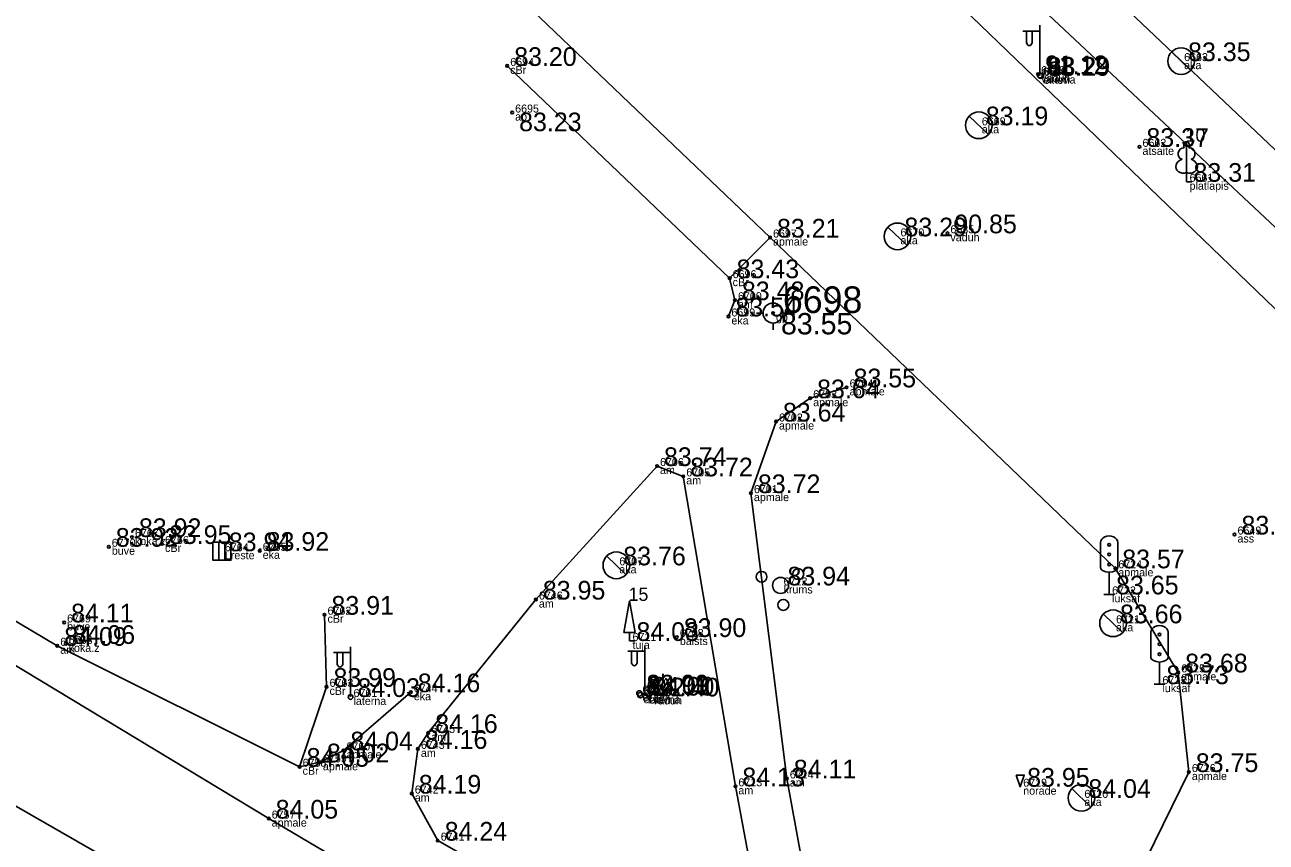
# Model space of a CAD drawing. Extents: x 614911 to 615803, y 262110 to 264311.
# Drawn here: x 615198.38 to 615244.91, y 262569.35 to 262599.99 of the extents above; entities that cross this region are included whole.
import ezdxf

# ---------------------------------------------------------------- set-up
doc = ezdxf.new("R2010")
doc.units = 0
for name, color, linetype in [('Level 1', 7, 'Continuous'), ('Level 12', 7, 'Continuous'), ('Level 16', 7, 'Continuous'), ('Level 19', 7, 'Continuous'), ('Level 37', 7, 'Continuous'), ('Level 44', 7, 'Continuous'), ('Level 48', 7, 'Continuous'), ('Level 53', 7, 'Continuous'), ('Level 54', 7, 'Continuous'), ('Level 57', 7, 'Continuous'), ('Level 58', 7, 'Continuous'), ('Level 7', 7, 'Continuous')]:
    doc.layers.add(name, color=color, linetype=linetype)

msp = doc.modelspace()

# ---------------------------------------------------------------- linework, layer by layer
at = {"layer": 'Level 1'}
for p, q in [((615241.925, 262594.455), (615241.925, 262594.108)), ((615241.925, 262594.108), (615242.125, 262594.108)), ((615221.048, 262576.897), (615221.048, 262577.217)), ((615221.048, 262576.897), (615221.258, 262576.897))]:
    msp.add_line(p, q, dxfattribs=at)
for points in [[(615241.925, 262595.608), (615241.925, 262594.455)], [(615242.015, 262595.376), (615242.014, 262595.377)]]:
    msp.add_lwpolyline(points, dxfattribs=at)
msp.add_lwpolyline([(615220.838, 262577.217), (615221.258, 262577.217), (615221.048, 262578.397)], close=True, dxfattribs=at)
for centre, radius in [((615225.994, 262579.301), 0.204), ((615226.708, 262578.977), 0.301), ((615227.369, 262579.402), 0.207), ((615226.811, 262578.249), 0.205)]:
    msp.add_circle(centre, radius, dxfattribs=at)
for centre, major_axis, ratio, start_param, end_param in [((615241.925, 262595.458), (0, -0.15), 0.707107, 3.14537, 5.287485), ((615241.925, 262595.458), (0, -0.15), 0.707107, 0.995701, 3.137816), ((615241.797, 262595.163), (-0.039, -0.212), 0.861323, 3.141593, 6.283185), ((615242.053, 262595.163), (0.039, -0.212), 0.861323, 0, 3.141593), ((615241.835, 262594.701), (0.307, 0.095), 0.814445, 1.570796, 4.752015), ((615242.015, 262594.701), (-0.307, 0.095), 0.814445, 1.531171, 4.712389)]:
    msp.add_ellipse(centre, major_axis=major_axis, ratio=ratio, start_param=start_param, end_param=end_param, dxfattribs=at)
at = {"layer": 'Level 12'}
for p, q in [((615241.362, 262598.978), (615242.08, 262598.282)), ((615241.721, 262598.63), (615241.72, 262598.629)), ((615233.78, 262596.572), (615234.498, 262595.876)), ((615234.139, 262596.224), (615234.138, 262596.223)), ((615230.732, 262592.41), (615231.45, 262591.714)), ((615231.091, 262592.062), (615231.09, 262592.061)), ((615220.194, 262580.079), (615220.912, 262579.383)), ((615220.553, 262579.731), (615220.552, 262579.73)), ((615238.81, 262577.906), (615239.528, 262577.21)), ((615239.169, 262577.558), (615239.168, 262577.557)), ((615237.624, 262571.362), (615238.342, 262570.666)), ((615237.983, 262571.014), (615237.982, 262571.013))]:
    msp.add_line(p, q, dxfattribs=at)
for centre in [(615241.721, 262598.63), (615234.139, 262596.224), (615231.091, 262592.062), (615220.553, 262579.731), (615239.169, 262577.558), (615237.983, 262571.014)]:
    msp.add_circle(centre, 0.5, dxfattribs=at)
at = {"layer": 'Level 16'}
for p, q in [((615238.701, 262580.591), (615238.701, 262579.645)), ((615239.343, 262580.591), (615239.343, 262579.645)), ((615239.022, 262579.471), (615239.022, 262578.642)), ((615238.822, 262578.642), (615239.022, 262578.642)), ((615239.022, 262578.642), (615239.222, 262578.642)), ((615240.588, 262577.227), (615240.588, 262576.281)), ((615241.23, 262577.227), (615241.23, 262576.281)), ((615240.909, 262576.107), (615240.909, 262575.278)), ((615240.709, 262575.278), (615240.909, 262575.278)), ((615240.909, 262575.278), (615241.109, 262575.278))]:
    msp.add_line(p, q, dxfattribs=at)
for centre in [(615239.022, 262580.502), (615239.022, 262580.142), (615239.022, 262579.762), (615240.909, 262577.138), (615240.909, 262576.778), (615240.909, 262576.398)]:
    msp.add_circle(centre, 0.05, dxfattribs=at)
for centre, ratio, start_param, end_param in [((615239.022, 262580.591), 0.760342, 0, 3.141593), ((615239.022, 262579.645), 0.542056, 3.141593, 6.283185), ((615240.909, 262577.227), 0.760342, 0, 3.141593), ((615240.909, 262576.281), 0.542056, 3.141593, 6.283185)]:
    msp.add_ellipse(centre, major_axis=(0.321, 0), ratio=ratio, start_param=start_param, end_param=end_param, dxfattribs=at)
at = {"layer": 'Level 19'}
for p, q in [((615226.425, 262589.563), (615226.425, 262589.813)), ((615225.8, 262589.188), (615226.05, 262589.188)), ((615226.8, 262589.188), (615227.05, 262589.188)), ((615226.425, 262588.563), (615226.425, 262588.813))]:
    msp.add_line(p, q, dxfattribs=at)
for radius in [0.375, 0.05]:
    msp.add_circle((615226.425, 262589.188), radius, dxfattribs=at)
at = {"layer": 'Level 37'}
msp.add_line((615224.8, 262590.494), (615226.313, 262592.017), dxfattribs=at)
for points in [[(615229.035, 262607.61), (615228.582, 262606.525), (615229.192, 262604.807), (615247.893, 262586.794), (615249.003, 262588.575), (615248.819, 262589.059)], [(615226.458, 262563.733), (615225.015, 262571.448), (615223.063, 262583.066), (615222.077, 262583.453), (615217.538, 262578.448), (615213.503, 262573.447), (615213.116, 262572.851), (615212.887, 262571.176), (615213.858, 262569.412), (615221.288, 262565.152), (615224.887, 262563.845)]]:
    msp.add_lwpolyline(points, close=True, dxfattribs=at)
for points in [[(615281.103, 262578.829), (615274.198, 262576.959), (615266.8, 262577.244), (615261.124, 262580.267), (615236.703, 262603.415), (615232.202, 262607.71)], [(615229.462, 262561.056), (615236.907, 262564.656), (615239.467, 262566.806), (615242.011, 262571.983), (615241.612, 262575.718), (615239.254, 262579.62), (615226.313, 262592.017), (615217.13, 262600.787)], [(615216.464, 262598.45), (615224.8, 262590.494), (615224.999, 262589.668), (615224.753, 262589.059)], [(615208.683, 262572.181), (615199.6, 262576.716), (615192.986, 262580.641), (615185.727, 262585.487), (615185.75, 262586.016), (615181.977, 262588.379), (615178.877, 262590.297)], [(615177.494, 262588.45), (615192.153, 262579.526), (615207.523, 262570.238), (615220.011, 262562.863), (615221.634, 262562.045), (615224.342, 262561.098), (615229.242, 262561.003), (615229.462, 262561.056)], [(615229.183, 262586.402), (615227.818, 262585.994), (615226.537, 262585.121), (615225.598, 262582.438), (615226.943, 262571.742), (615228.392, 262563.814), (615235.188, 262566.685)], [(615216.216, 262560.276), (615189.988, 262575.33), (615174.111, 262583.87)], [(615212.85, 262574.975), (615210.324, 262572.795), (615209.444, 262572.348), (615208.683, 262572.181), (615209.693, 262575.176), (615209.616, 262577.88)]]:
    msp.add_lwpolyline(points, dxfattribs=at)
at = {"layer": 'Level 44'}
for p, q in [((615236.426, 262599.757), (615235.791, 262599.752)), ((615235.926, 262599.753), (615235.926, 262599.361)), ((615236.136, 262599.755), (615236.136, 262599.361)), ((615236.426, 262598.09), (615236.426, 262599.973)), ((615210.591, 262576.464), (615209.956, 262576.459)), ((615210.091, 262576.46), (615210.091, 262576.068)), ((615210.301, 262576.462), (615210.301, 262576.068)), ((615210.591, 262574.797), (615210.591, 262576.68)), ((615221.622, 262576.515), (615220.987, 262576.51)), ((615221.122, 262576.511), (615221.122, 262576.119)), ((615221.332, 262576.513), (615221.332, 262576.119)), ((615221.622, 262574.848), (615221.622, 262576.731))]:
    msp.add_line(p, q, dxfattribs=at)
for centre in [(615236.426, 262598.09), (615210.591, 262574.797), (615221.622, 262574.848)]:
    msp.add_circle(centre, 0.09, dxfattribs=at)
for centre in [(615236.031, 262599.361), (615210.196, 262576.068), (615221.227, 262576.119)]:
    msp.add_ellipse(centre, major_axis=(0, 0.151), ratio=0.695971, start_param=1.570796, end_param=4.712389, dxfattribs=at)
at = {"layer": 'Level 48'}
for p, q in [((615205.655, 262580.597), (615205.655, 262579.922)), ((615205.88, 262580.597), (615205.88, 262579.922))]:
    msp.add_line(p, q, dxfattribs=at)
msp.add_lwpolyline([(615205.43, 262580.597), (615206.105, 262580.597), (615206.105, 262579.922), (615205.43, 262579.922)], close=True, dxfattribs=at)
at = {"layer": 'Level 57'}
for centre in [(615216.464, 262598.45), (615236.359, 262598.14), (615216.648, 262596.702), (615240.16, 262595.416), (615232.961, 262592.177), (615226.313, 262592.017), (615224.8, 262590.494), (615224.999, 262589.668), (615224.753, 262589.059), (615229.183, 262586.402), (615227.818, 262585.994), (615226.537, 262585.121), (615222.077, 262583.453), (615223.063, 262583.066), (615225.598, 262582.438), (615202.399, 262580.791), (615203.526, 262580.532), (615243.722, 262580.886), (615201.531, 262580.427), (615207.186, 262580.275), (615239.254, 262579.62), (615217.538, 262578.448), (615209.616, 262577.88), (615199.856, 262577.592), (615222.821, 262577.044), (615199.6, 262576.716), (615199.914, 262576.785), (615241.612, 262575.718), (615209.693, 262575.176), (615212.85, 262574.975), (615221.81, 262574.817), (615213.503, 262573.447), (615210.324, 262572.795), (615213.116, 262572.851), (615208.683, 262572.181), (615209.444, 262572.348), (615226.943, 262571.742), (615242.011, 262571.983), (615225.015, 262571.448), (615212.887, 262571.176), (615207.523, 262570.238), (615213.858, 262569.412)]:
    msp.add_circle(centre, 0.05, dxfattribs=at)
at = {"layer": 'Level 58'}
msp.add_lwpolyline([(615235.54, 262571.867), (615235.84, 262571.867), (615235.69, 262571.434)], close=True, dxfattribs=at)
for centre in [(615216.464, 262598.45), (615236.359, 262598.14), (615216.648, 262596.702), (615240.16, 262595.416), (615232.961, 262592.177), (615226.313, 262592.017), (615224.8, 262590.494), (615224.999, 262589.668), (615224.753, 262589.059), (615229.183, 262586.402), (615227.818, 262585.994), (615226.537, 262585.121), (615222.077, 262583.453), (615223.063, 262583.066), (615225.598, 262582.438), (615202.399, 262580.791), (615203.526, 262580.532), (615243.722, 262580.886), (615201.531, 262580.427), (615207.186, 262580.275), (615239.254, 262579.62), (615217.538, 262578.448), (615209.616, 262577.88), (615199.856, 262577.592), (615222.821, 262577.044), (615199.6, 262576.716), (615199.914, 262576.785), (615241.612, 262575.718), (615209.693, 262575.176), (615212.85, 262574.975), (615221.81, 262574.817), (615213.503, 262573.447), (615210.324, 262572.795), (615213.116, 262572.851), (615208.683, 262572.181), (615209.444, 262572.348), (615226.943, 262571.742), (615242.011, 262571.983), (615225.015, 262571.448), (615212.887, 262571.176), (615207.523, 262570.238), (615213.858, 262569.412)]:
    msp.add_circle(centre, 0.05, dxfattribs=at)
at = {"layer": 'Level 7'}
for centre in [(615236.457, 262598.079), (615221.418, 262574.929), (615221.453, 262574.863)]:
    msp.add_circle(centre, 0.1, dxfattribs=at)

# ---------------------------------------------------------------- texts
at = {"layer": 'Level 1'}
for s, p in [(' 10', (615241.7, 262595.608)), (' 15', (615220.823, 262578.397))]:
    msp.add_text(s, height=0.5, dxfattribs=at).set_placement(p)
at = {"layer": 'Level 19'}
for s, height, p in [(' 6698', 1, (615226.425, 262589.188)), (' 83.55', 0.8, (615226.425, 262588.388))]:
    msp.add_text(s, height=height, dxfattribs=at).set_placement(p)
at = {"layer": 'Level 48'}
msp.add_text(' 83.94', height=0.7, dxfattribs=at).set_placement((615205.768, 262580.259))
at = {"layer": 'Level 53'}
for s, p in [(' cBr', (615216.464, 262598.15)), (' aka', (615241.721, 262598.33)), (' vaduh', (615236.359, 262597.84)), (' laterna', (615236.426, 262597.79)), (' el.iev', (615236.457, 262597.779)), (' ap', (615216.648, 262596.402)), (' aka', (615234.139, 262595.924)), (' atsaite', (615240.16, 262595.116)), (' platlapis', (615241.925, 262593.808)), (' apmale', (615226.313, 262591.717)), (' aka', (615231.091, 262591.762)), (' vaduh', (615232.961, 262591.877)), (' cBr', (615224.8, 262590.194)), (' am', (615224.999, 262589.368)), (' eka', (615224.753, 262588.759)), (' gp', (615226.425, 262588.888)), (' apmale', (615229.183, 262586.102)), (' apmale', (615227.818, 262585.694)), (' apmale', (615226.537, 262584.821)), (' am', (615222.077, 262583.153)), (' am', (615223.063, 262582.766)), (' apmale', (615225.598, 262582.138)), (' koka.z', (615202.399, 262580.491)), (' ass', (615243.722, 262580.586)), (' buve', (615201.531, 262580.127)), (' cBr', (615203.526, 262580.232)), (' Lreste', (615205.768, 262579.959)), (' eka', (615207.186, 262579.975)), (' aka', (615220.553, 262579.431)), (' apmale', (615239.254, 262579.32)), (' krums', (615226.708, 262578.677)), (' am', (615217.538, 262578.148)), (' luksaf', (615239.022, 262578.342)), (' cBr', (615209.616, 262577.58)), (' buve', (615199.856, 262577.292)), (' aka', (615239.169, 262577.258)), (' tuja', (615221.048, 262576.597)), (' balsts', (615222.821, 262576.744)), (' am', (615199.6, 262576.416)), (' koka.z', (615199.914, 262576.485)), (' apmale', (615241.612, 262575.418)), (' cBr', (615209.693, 262574.876)), (' luksaf', (615240.909, 262574.978)), (' laterna', (615210.591, 262574.497)), (' eka', (615212.85, 262574.675)), (' el.iev', (615221.418, 262574.629)), (' el.iev', (615221.453, 262574.563)), (' laterna', (615221.622, 262574.548)), (' vaduh', (615221.81, 262574.517)), (' am', (615213.503, 262573.147)), (' apmale', (615210.324, 262572.495)), (' am', (615213.116, 262572.551)), (' apmale', (615209.444, 262572.048)), (' cBr', (615208.683, 262571.881)), (' apmale', (615242.011, 262571.683)), (' am', (615225.015, 262571.148)), (' am', (615226.943, 262571.442)), (' norade', (615235.69, 262571.134)), (' am', (615212.887, 262570.876)), (' aka', (615237.983, 262570.714)), (' apmale', (615207.523, 262569.938))]:
    msp.add_text(s, height=0.3, dxfattribs=at).set_placement(p)
at = {"layer": 'Level 54'}
for s, p in [(' 6694', (615216.464, 262598.45)), (' 6663', (615241.721, 262598.63)), (' 6668', (615236.359, 262598.14)), (' 6666', (615236.426, 262598.09)), (' 6667', (615236.457, 262598.079)), (' 6695', (615216.648, 262596.702)), (' 6669', (615234.139, 262596.224)), (' 6662', (615240.16, 262595.416)), (' 6661', (615241.925, 262594.108)), (' 6697', (615226.313, 262592.017)), (' 6670', (615231.091, 262592.062)), (' 6635', (615232.961, 262592.177)), (' 6696', (615224.8, 262590.494)), (' 6700', (615224.999, 262589.668)), (' 6699', (615224.753, 262589.059)), (' 6704', (615229.183, 262586.402)), (' 6703', (615227.818, 262585.994)), (' 6702', (615226.537, 262585.121)), (' 6706', (615222.077, 262583.453)), (' 6705', (615223.063, 262583.066)), (' 6701', (615225.598, 262582.438)), (' 6767', (615202.399, 262580.791)), (' 6649', (615243.722, 262580.886)), (' 6770', (615201.531, 262580.427)), (' 6766', (615203.526, 262580.532)), (' 6765', (615207.186, 262580.275)), (' 6764', (615205.768, 262580.259)), (' 6707', (615220.553, 262579.731)), (' 6724', (615239.254, 262579.62)), (' 6712', (615226.708, 262578.977)), (' 6746', (615217.538, 262578.448)), (' 6722', (615239.022, 262578.642)), (' 6769', (615199.856, 262577.592)), (' 6762', (615209.616, 262577.88)), (' 6721', (615239.169, 262577.558)), (' 6708', (615222.821, 262577.044)), (' 6771', (615199.6, 262576.716)), (' 6768', (615199.914, 262576.785)), (' 6711', (615221.048, 262576.897)), (' 6725', (615241.612, 262575.718)), (' 6763', (615209.693, 262575.176)), (' 6723', (615240.909, 262575.278)), (' 6761', (615210.591, 262574.797)), (' 6744', (615212.85, 262574.975)), (' 6747', (615221.418, 262574.929)), (' 6710', (615221.453, 262574.863)), (' 6709', (615221.622, 262574.848)), (' 6730', (615221.81, 262574.817)), (' 6745', (615213.503, 262573.447)), (' 6743', (615213.116, 262572.851)), (' 6760', (615210.324, 262572.795)), (' 6758', (615208.683, 262572.181)), (' 6759', (615209.444, 262572.348)), (' 6726', (615242.011, 262571.983)), (' 6713', (615225.015, 262571.448)), (' 6714', (615226.943, 262571.742)), (' 6742', (615212.887, 262571.176)), (' 6719', (615235.69, 262571.434)), (' 6720', (615237.983, 262571.014)), (' 6757', (615207.523, 262570.238)), (' 6741', (615213.858, 262569.412))]:
    msp.add_text(s, height=0.3, dxfattribs=at).set_placement(p)
at = {"layer": 'Level 58'}
for s, p in [(' 83.35', (615241.721, 262598.63)), (' 83.20', (615216.464, 262598.45)), (' 91.12', (615236.359, 262598.14)), (' 83.29', (615236.426, 262598.09)), (' 83.29', (615236.457, 262598.079)), (' 83.19', (615234.139, 262596.224)), (' 83.23', (615216.648, 262596.002)), (' 83.37', (615240.16, 262595.416)), (' 83.31', (615241.925, 262594.108)), (' 83.21', (615226.313, 262592.017)), (' 83.29', (615231.091, 262592.062)), (' 90.85', (615232.961, 262592.177)), (' 83.43', (615224.8, 262590.494)), (' 83.48', (615224.999, 262589.668)), (' 83.54', (615224.753, 262589.059)), (' 83.55', (615229.183, 262586.402)), (' 83.64', (615227.818, 262585.994)), (' 83.64', (615226.537, 262585.121)), (' 83.74', (615222.077, 262583.453)), (' 83.72', (615223.063, 262583.066)), (' 83.72', (615225.598, 262582.438)), (' 83.46', (615243.722, 262580.886)), (' 83.92', (615201.531, 262580.427)), (' 83.92', (615202.399, 262580.791)), (' 83.95', (615203.526, 262580.532)), (' 83.92', (615207.186, 262580.275)), (' 83.76', (615220.553, 262579.731)), (' 83.57', (615239.254, 262579.62)), (' 83.94', (615226.708, 262578.977)), (' 83.65', (615239.022, 262578.642)), (' 83.95', (615217.538, 262578.448)), (' 84.11', (615199.856, 262577.592)), (' 83.91', (615209.616, 262577.88)), (' 83.66', (615239.169, 262577.558)), (' 84.09', (615199.6, 262576.716)), (' 84.06', (615199.914, 262576.785)), (' 84.03', (615221.048, 262576.897)), (' 83.90', (615222.821, 262577.044)), (' 83.68', (615241.612, 262575.718)), (' 83.73', (615240.909, 262575.278)), (' 83.99', (615209.693, 262575.176)), (' 84.03', (615210.591, 262574.797)), (' 84.16', (615212.85, 262574.975)), (' 83.99', (615221.418, 262574.929)), (' 84.03', (615221.453, 262574.863)), (' 84.00', (615221.622, 262574.848)), (' 92.40', (615221.81, 262574.817)), (' 84.16', (615213.503, 262573.447)), (' 84.04', (615210.324, 262572.795)), (' 84.16', (615213.116, 262572.851)), (' 84.05', (615208.683, 262572.181)), (' 84.02', (615209.444, 262572.348)), (' 83.75', (615242.011, 262571.983)), (' 84.11', (615226.943, 262571.742)), (' 84.19', (615212.887, 262571.176)), (' 84.13', (615225.015, 262571.448)), (' 83.95', (615235.69, 262571.434)), (' 84.04', (615237.983, 262571.014)), (' 84.05', (615207.523, 262570.238)), (' 84.24', (615213.858, 262569.412))]:
    msp.add_text(s, height=0.7, dxfattribs=at).set_placement(p)
at = {"layer": 'Level 7'}
for p in [(615236.457, 262598.079), (615221.418, 262574.929), (615221.453, 262574.863)]:
    msp.add_text(' el.', height=0.7, dxfattribs=at).set_placement(p)

doc.saveas('drawing.dxf')
